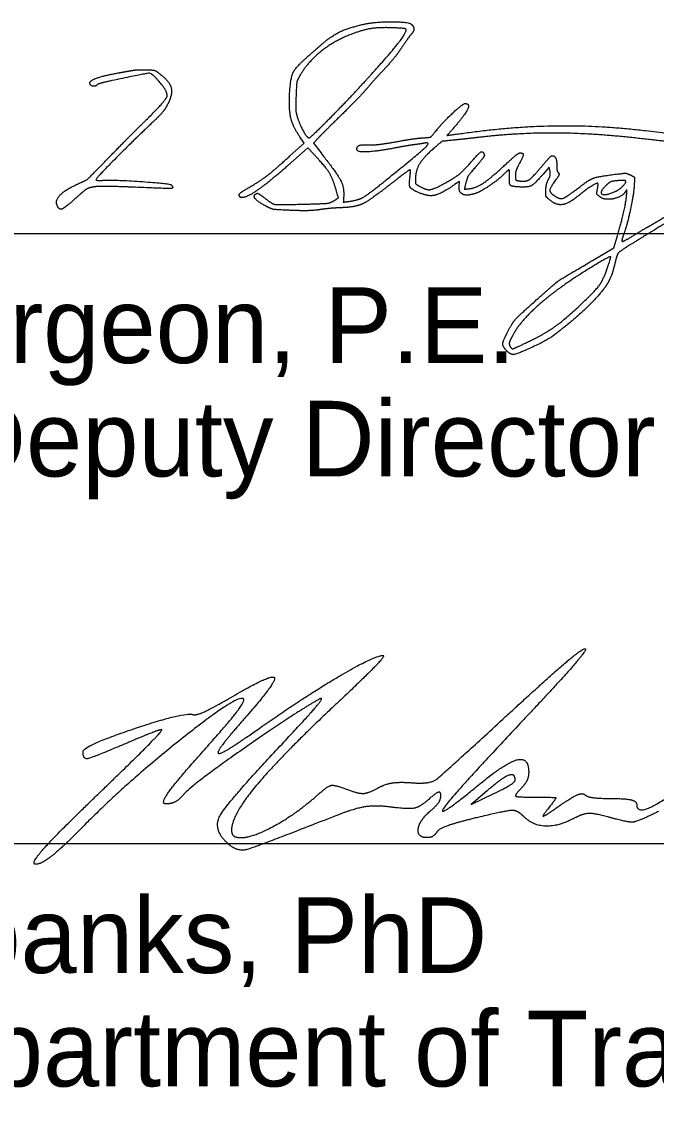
# Model space of a CAD drawing. Extents: x 0 to 34, y 0 to 22.
# Drawn here: x 25.538 to 26.712, y 5.969 to 7.983 of the extents above; entities that cross this region are included whole.
import ezdxf

# ---------------------------------------------------------------- set-up
doc = ezdxf.new("R2010")
doc.units = 0
doc.layers.add('SH_Data', color=7, linetype='Continuous')
doc.layers.add('SH_Text', color=7, linetype='Continuous')

msp = doc.modelspace()

# ---------------------------------------------------------------- linework, layer by layer
at = {"layer": 'SH_Data'}
for p, q in [((24.4745, 7.5907), (27.9745, 7.5907)), ((24.4745, 6.4613), (27.9745, 6.4613))]:
    msp.add_line(p, q, dxfattribs=at)
for points in [[(26.0343, 7.7342), (26.0607, 7.758), (26.0526, 7.7697)], [(26.0877, 7.7684), (26.0776, 7.758), (26.0893, 7.7429)], [(26.0783, 7.7374), (26.0674, 7.7489), (26.0305, 7.7162)], [(26.5156, 7.7054), (26.5143, 7.7133), (26.5027, 7.7002)], [(26.3475, 7.6783), (26.3479, 7.6871), (26.339, 7.681)], [(26.5943, 7.5406), (26.6335, 7.5637), (26.6403, 7.5865)]]:
    msp.add_lwpolyline(points, dxfattribs=at)
for points in [[(26.0927, 7.9404), (26.1103, 7.956), (26.142, 7.9714), (26.1696, 7.9777)], [(26.1696, 7.9777), (26.1908, 7.9826), (26.2538, 7.9826), (26.2591, 7.9778)], [(26.2591, 7.9778), (26.2638, 7.9735), (26.2637, 7.9649), (26.2588, 7.9595)], [(26.1451, 7.9583), (26.1151, 7.9466), (26.0672, 7.9077), (26.0534, 7.884)], [(26.2257, 7.9713), (26.1998, 7.9724), (26.1679, 7.9673), (26.1451, 7.9583)], [(26.2119, 7.9155), (26.2286, 7.9344), (26.2493, 7.9628), (26.2495, 7.9672)], [(26.2495, 7.9672), (26.2496, 7.9693), (26.2423, 7.9706), (26.2257, 7.9713)], [(26.2588, 7.9595), (26.2568, 7.9573), (26.249, 7.9464), (26.2415, 7.9353)], [(26.0742, 7.9244), (26.0819, 7.9311), (26.0902, 7.9382), (26.0927, 7.9404)], [(26.2415, 7.9353), (26.234, 7.9241), (26.2202, 7.9069), (26.2109, 7.8971)], [(26.0334, 7.8443), (26.0349, 7.8786), (26.0459, 7.9001), (26.0742, 7.9244)], [(26.1013, 7.797), (26.1287, 7.8244), (26.178, 7.8771), (26.2119, 7.9155)], [(25.7419, 7.8924), (25.7478, 7.8934), (25.7597, 7.894), (25.7686, 7.8937)], [(25.7686, 7.8937), (25.7822, 7.8932), (25.7861, 7.8919), (25.7949, 7.885)], [(26.2109, 7.8971), (26.2016, 7.8873), (26.1866, 7.8706), (26.1776, 7.8602)], [(25.6643, 7.867), (25.6634, 7.8687), (25.6643, 7.8714), (25.6664, 7.8732)], [(25.6664, 7.8732), (25.6704, 7.8767), (25.6966, 7.8843), (25.718, 7.8881)], [(25.7047, 7.8735), (25.6904, 7.8704), (25.678, 7.8669), (25.6772, 7.8657)], [(25.7911, 7.8733), (25.7791, 7.8872), (25.7674, 7.8872), (25.7047, 7.8735)], [(25.718, 7.8881), (25.7253, 7.8894), (25.7361, 7.8913), (25.7419, 7.8924)], [(25.7684, 7.8009), (25.8042, 7.8359), (25.8093, 7.8522), (25.7911, 7.8733)], [(25.7949, 7.885), (25.8131, 7.8705), (25.8169, 7.8451), (25.8043, 7.8229)], [(26.0534, 7.884), (26.0476, 7.874), (26.0465, 7.8688), (26.0455, 7.8447)], [(25.6772, 7.8657), (25.6752, 7.8627), (25.6662, 7.8636), (25.6643, 7.867)], [(26.1776, 7.8602), (26.1686, 7.8497), (26.1469, 7.8271), (26.1295, 7.81)], [(26.0526, 7.7697), (26.0403, 7.7873), (26.0323, 7.8184), (26.0334, 7.8443)], [(26.0455, 7.8447), (26.0446, 7.8241), (26.0454, 7.8136), (26.0486, 7.8038)], [(25.8043, 7.8229), (25.8017, 7.8184), (25.7895, 7.8052), (25.777, 7.7934)], [(26.3073, 7.7838), (26.3189, 7.7982), (26.3549, 7.8314), (26.3585, 7.8312)], [(26.3585, 7.8312), (26.3677, 7.8308), (26.3594, 7.8121), (26.34, 7.7892)], [(25.777, 7.7934), (25.7404, 7.7588), (25.6742, 7.6915), (25.6752, 7.6898)], [(25.7051, 7.7373), (25.7254, 7.7581), (25.7539, 7.7868), (25.7684, 7.8009)], [(26.0486, 7.8038), (26.053, 7.7904), (26.0663, 7.7676), (26.0697, 7.7674)], [(26.0697, 7.7674), (26.0708, 7.7674), (26.085, 7.7807), (26.1013, 7.797)], [(26.1295, 7.81), (26.112, 7.7928), (26.0932, 7.7741), (26.0877, 7.7684)], [(26.2783, 7.7675), (26.294, 7.7686), (26.2956, 7.7696), (26.3073, 7.7838)], [(26.34, 7.7892), (26.3252, 7.7718), (26.3244, 7.7721), (26.3703, 7.7782)], [(26.3703, 7.7782), (26.4917, 7.7944), (26.7153, 7.7829), (26.8721, 7.7525)], [(26.6857, 7.766), (26.598, 7.776), (26.4573, 7.7771), (26.383, 7.7684)], [(26.1582, 7.7463), (26.1585, 7.7522), (26.1672, 7.7553), (26.1819, 7.7546)], [(26.1819, 7.7546), (26.1891, 7.7543), (26.2103, 7.7568), (26.2291, 7.7602)], [(26.2107, 7.6883), (26.2753, 7.7404), (26.296, 7.7609), (26.2805, 7.7573)], [(26.2652, 7.755), (26.2594, 7.7543), (26.2427, 7.7515), (26.2281, 7.7487)], [(26.2291, 7.7602), (26.2478, 7.7636), (26.2699, 7.7669), (26.2783, 7.7675)], [(26.2805, 7.7573), (26.2779, 7.7567), (26.2711, 7.7557), (26.2652, 7.755)], [(26.338, 7.7634), (26.316, 7.7612), (26.3153, 7.7609), (26.2994, 7.7471)], [(26.383, 7.7684), (26.3706, 7.7669), (26.3504, 7.7647), (26.338, 7.7634)], [(26.7749, 7.7563), (26.7583, 7.7579), (26.7182, 7.7623), (26.6857, 7.766)], [(25.6405, 7.6817), (25.6583, 7.6898), (25.6619, 7.6929), (25.7051, 7.7373)], [(25.9572, 7.675), (25.9807, 7.6889), (26.0019, 7.7051), (26.0343, 7.7342)], [(26.1186, 7.6749), (26.113, 7.6937), (26.0989, 7.7155), (26.0783, 7.7374)], [(26.0893, 7.7429), (26.1215, 7.7017), (26.135, 7.6757), (26.1336, 7.6572)], [(26.2281, 7.7487), (26.1928, 7.7421), (26.158, 7.7409), (26.1582, 7.7463)], [(26.2994, 7.7471), (26.2812, 7.7313), (26.2671, 7.7079), (26.2665, 7.6924)], [(26.371, 7.7245), (26.3841, 7.7397), (26.3918, 7.7435), (26.394, 7.7359)], [(26.394, 7.7359), (26.3944, 7.7343), (26.3884, 7.7257), (26.3805, 7.7168)], [(26.4348, 7.7197), (26.4468, 7.7309), (26.4582, 7.7399), (26.4601, 7.7399)], [(26.4601, 7.7399), (26.4664, 7.7396), (26.4659, 7.733), (26.4584, 7.7192)], [(26.5012, 7.7158), (26.5092, 7.7255), (26.5171, 7.7338), (26.5186, 7.7343)], [(26.5186, 7.7343), (26.5233, 7.7356), (26.5284, 7.7256), (26.5281, 7.7157)], [(26.0305, 7.7162), (25.9965, 7.6862), (25.9539, 7.6566), (25.9451, 7.657)], [(26.3167, 7.6814), (26.3391, 7.6936), (26.355, 7.7062), (26.371, 7.7245)], [(26.3805, 7.7168), (26.3661, 7.7003), (26.3621, 7.6936), (26.3588, 7.68)], [(26.3667, 7.6736), (26.3793, 7.6751), (26.4064, 7.6934), (26.4348, 7.7197)], [(26.4584, 7.7192), (26.454, 7.711), (26.4512, 7.7021), (26.4515, 7.6972)], [(26.4599, 7.6877), (26.4711, 7.6861), (26.4839, 7.6948), (26.5012, 7.7158)], [(26.5281, 7.7157), (26.5279, 7.7106), (26.5291, 7.7049), (26.5307, 7.7032)], [(26.2561, 7.7086), (26.2551, 7.7083), (26.2369, 7.6946), (26.2157, 7.6781)], [(26.2694, 7.6676), (26.2581, 7.673), (26.2547, 7.6805), (26.2565, 7.6964)], [(26.2565, 7.6964), (26.2573, 7.7034), (26.2571, 7.7089), (26.2561, 7.7086)], [(26.2665, 7.6924), (26.2661, 7.6842), (26.2673, 7.6819), (26.2736, 7.6783)], [(26.4312, 7.7013), (26.4218, 7.6916), (26.3893, 7.669), (26.3799, 7.6655)], [(26.4404, 7.6961), (26.4409, 7.7078), (26.4387, 7.709), (26.4312, 7.7013)], [(26.4604, 7.6766), (26.4449, 7.6773), (26.4398, 7.6822), (26.4404, 7.6961)], [(26.4515, 7.6972), (26.4519, 7.6901), (26.4531, 7.6887), (26.4599, 7.6877)], [(26.5027, 7.7002), (26.4864, 7.6819), (26.4758, 7.676), (26.4604, 7.6766)], [(26.5125, 7.6901), (26.5151, 7.6946), (26.5163, 7.7007), (26.5156, 7.7054)], [(26.5307, 7.7032), (26.5329, 7.7008), (26.5319, 7.6977), (26.5266, 7.6903)], [(26.5711, 7.6772), (26.5879, 7.6901), (26.604, 7.696), (26.6327, 7.6997)], [(26.6327, 7.6997), (26.6529, 7.7022), (26.6579, 7.7021), (26.6644, 7.6989)], [(26.6644, 7.6989), (26.6715, 7.6954), (26.6721, 7.694), (26.6715, 7.6819)], [(25.6045, 7.6403), (25.5988, 7.6504), (25.6167, 7.6709), (25.6405, 7.6817)], [(25.6706, 7.6767), (25.6612, 7.6749), (25.6544, 7.6706), (25.6378, 7.6558)], [(25.7475, 7.6761), (25.7118, 7.6776), (25.6772, 7.6779), (25.6706, 7.6767)], [(25.6752, 7.6898), (25.6757, 7.6889), (25.6824, 7.6886), (25.6901, 7.6891)], [(25.6901, 7.6891), (25.7081, 7.6902), (25.8121, 7.6831), (25.8144, 7.6807)], [(25.8144, 7.6807), (25.8202, 7.6743), (25.8088, 7.6735), (25.7475, 7.6761)], [(25.9404, 7.6608), (25.9396, 7.663), (25.9458, 7.6683), (25.9572, 7.675)], [(26.1187, 7.6531), (26.124, 7.6567), (26.124, 7.6569), (26.1186, 7.6749)], [(26.1429, 7.6499), (26.1607, 7.6523), (26.1786, 7.6624), (26.2107, 7.6883)], [(26.2157, 7.6781), (26.1935, 7.661), (26.1717, 7.6463), (26.1646, 7.6437)], [(26.339, 7.681), (26.3138, 7.6634), (26.2886, 7.6586), (26.2694, 7.6676)], [(26.2736, 7.6783), (26.2861, 7.6711), (26.2997, 7.6721), (26.3167, 7.6814)], [(26.3501, 7.6662), (26.3484, 7.668), (26.3473, 7.6734), (26.3475, 7.6783)], [(26.3588, 7.68), (26.3569, 7.6725), (26.3571, 7.6725), (26.3667, 7.6736)], [(26.5078, 7.6709), (26.5081, 7.6774), (26.5102, 7.686), (26.5125, 7.6901)], [(26.5266, 7.6903), (26.5159, 7.6755), (26.5143, 7.6675), (26.5211, 7.6623)], [(26.5211, 7.6623), (26.5326, 7.6535), (26.5453, 7.6573), (26.5711, 7.6772)], [(26.6035, 7.6836), (26.6009, 7.6837), (26.5812, 7.6713), (26.5733, 7.6645)], [(26.6076, 7.6587), (26.6026, 7.6626), (26.6019, 7.6649), (26.6035, 7.6734)], [(26.6035, 7.6734), (26.6045, 7.6789), (26.6045, 7.6835), (26.6035, 7.6836)], [(26.62, 7.6801), (26.6068, 7.6675), (26.6163, 7.6598), (26.6352, 7.6678)], [(26.6407, 7.6883), (26.631, 7.6875), (26.6254, 7.6852), (26.62, 7.6801)], [(26.6352, 7.6678), (26.6436, 7.6714), (26.6576, 7.6856), (26.6552, 7.6882)], [(26.6552, 7.6882), (26.6546, 7.6889), (26.648, 7.689), (26.6407, 7.6883)], [(26.6715, 7.6819), (26.6708, 7.6661), (26.6594, 7.6105), (26.6532, 7.5928)], [(25.6378, 7.6558), (25.6179, 7.6381), (25.6082, 7.6336), (25.6045, 7.6403)], [(25.9451, 7.657), (25.9432, 7.6571), (25.941, 7.6588), (25.9404, 7.6608)], [(25.9916, 7.6402), (25.9745, 7.6491), (25.9654, 7.6608), (25.9725, 7.6648)], [(25.9725, 7.6648), (25.9738, 7.6655), (25.9793, 7.6626), (25.9848, 7.6583)], [(25.9848, 7.6583), (26.0014, 7.6453), (26.0103, 7.6436), (26.0547, 7.6447)], [(26.0547, 7.6447), (26.0972, 7.6457), (26.1101, 7.6474), (26.1187, 7.6531)], [(26.1336, 7.6572), (26.133, 7.6487), (26.1331, 7.6486), (26.1429, 7.6499)], [(26.3799, 7.6655), (26.3686, 7.6614), (26.3542, 7.6617), (26.3501, 7.6662)], [(26.514, 7.6534), (26.5085, 7.6581), (26.5074, 7.6614), (26.5078, 7.6709)], [(26.5733, 7.6645), (26.5524, 7.6466), (26.5273, 7.6419), (26.514, 7.6534)], [(26.6215, 7.6539), (26.6171, 7.654), (26.6109, 7.6562), (26.6076, 7.6587)], [(26.6547, 7.6673), (26.6508, 7.6612), (26.6318, 7.6535), (26.6215, 7.6539)], [(26.6403, 7.5865), (26.6483, 7.6133), (26.6571, 7.6529), (26.6575, 7.6641)], [(26.6575, 7.6641), (26.6577, 7.671), (26.6574, 7.6714), (26.6547, 7.6673)], [(26.0361, 7.6333), (26.0082, 7.6345), (26, 7.6358), (25.9916, 7.6402)], [(26.0888, 7.6346), (26.0786, 7.633), (26.0549, 7.6325), (26.0361, 7.6333)], [(26.1298, 7.6383), (26.1174, 7.6378), (26.099, 7.6361), (26.0888, 7.6346)], [(26.1646, 7.6437), (26.1578, 7.6413), (26.1421, 7.6388), (26.1298, 7.6383)], [(26.7047, 7.6073), (26.7163, 7.6137), (26.7457, 7.6334), (26.7579, 7.643)], [(26.7525, 7.6253), (26.7442, 7.6193), (26.7163, 7.6015), (26.6905, 7.5859)], [(26.6532, 7.5928), (26.6507, 7.5859), (26.6486, 7.5787), (26.6485, 7.5768)], [(26.6693, 7.5864), (26.6809, 7.5935), (26.6968, 7.6029), (26.7047, 7.6073)], [(26.6905, 7.5859), (26.6648, 7.5703), (26.6427, 7.5559), (26.6415, 7.5539)], [(26.6485, 7.5768), (26.6484, 7.575), (26.6578, 7.5793), (26.6693, 7.5864)], [(26.6415, 7.5539), (26.6402, 7.552), (26.6372, 7.5418), (26.6347, 7.5313)], [(26.4902, 7.4674), (26.5257, 7.499), (26.5364, 7.5065), (26.5943, 7.5406)], [(26.6278, 7.5475), (26.6265, 7.5489), (26.5653, 7.5117), (26.5422, 7.4955)], [(26.6099, 7.4989), (26.6144, 7.5065), (26.629, 7.5461), (26.6278, 7.5475)], [(26.6347, 7.5313), (26.6322, 7.5208), (26.6266, 7.506), (26.6222, 7.4983)], [(26.5422, 7.4955), (26.5082, 7.4715), (26.4594, 7.425), (26.4492, 7.4066)], [(26.519, 7.4143), (26.5382, 7.4269), (26.6028, 7.4871), (26.6099, 7.4989)], [(26.6222, 7.4983), (26.6141, 7.484), (26.5632, 7.4331), (26.5378, 7.4139)], [(26.4356, 7.4052), (26.4458, 7.4252), (26.4571, 7.438), (26.4902, 7.4674)], [(26.4739, 7.3894), (26.4883, 7.3962), (26.5085, 7.4074), (26.519, 7.4143)], [(26.5378, 7.4139), (26.5306, 7.4084), (26.5231, 7.4025), (26.521, 7.4008)], [(26.4354, 7.3735), (26.4279, 7.3816), (26.428, 7.3902), (26.4356, 7.4052)], [(26.4492, 7.4066), (26.4443, 7.3978), (26.4402, 7.3891), (26.4401, 7.3871)], [(26.521, 7.4008), (26.5135, 7.3945), (26.453, 7.3662), (26.4474, 7.3665)], [(26.4474, 7.3665), (26.4442, 7.3666), (26.4388, 7.3698), (26.4354, 7.3735)], [(26.4401, 7.3871), (26.44, 7.384), (26.4446, 7.3771), (26.4469, 7.377)], [(26.4469, 7.377), (26.4475, 7.377), (26.4596, 7.3826), (26.4739, 7.3894)]]:
    msp.add_open_spline(points, degree=2, dxfattribs=at)
at = {"layer": 'SH_Text'}
for p, q in [((26.4511, 6.5785), (26.4511, 6.5785)), ((25.674, 6.5474), (25.674, 6.5474))]:
    msp.add_line(p, q, dxfattribs=at)
msp.add_lwpolyline([(26.3994, 6.5588), (26.3698, 6.5332), (26.4105, 6.5528)], dxfattribs=at)
for points in [[(25.9792, 6.6755), (26.0598, 6.7322), (26.1911, 6.8094), (26.2068, 6.8094)], [(26.2068, 6.8094), (26.2117, 6.8094), (26.1704, 6.7668), (26.115, 6.7147)], [(26.4335, 6.696), (26.5085, 6.7651), (26.5745, 6.8217), (26.5803, 6.8217)], [(26.5803, 6.8217), (26.586, 6.8218), (26.534, 6.7617), (26.4646, 6.6881)], [(25.9203, 6.729), (25.999, 6.7752), (26.0113, 6.762), (25.952, 6.6947)], [(25.9483, 6.7288), (25.9387, 6.7384), (25.729, 6.5715), (25.6511, 6.4922)], [(26.0886, 6.7284), (26.0396, 6.7006), (25.8512, 6.5684), (25.838, 6.5524)], [(25.8546, 6.6998), (25.8602, 6.698), (25.8897, 6.7112), (25.9203, 6.729)], [(25.8705, 6.6284), (25.9168, 6.6802), (25.9518, 6.7253), (25.9483, 6.7288)], [(26.0234, 6.6494), (26.0696, 6.6987), (26.0989, 6.7342), (26.0886, 6.7284)], [(26.115, 6.7147), (26.0154, 6.621), (25.9261, 6.5128), (25.9261, 6.4858)], [(25.6513, 6.6313), (25.6515, 6.6418), (25.8389, 6.705), (25.8546, 6.6998)], [(25.952, 6.6947), (25.924, 6.6628), (25.9011, 6.6332), (25.9011, 6.6287)], [(26.2585, 6.5736), (26.292, 6.5708), (26.3155, 6.5872), (26.4335, 6.696)], [(26.4646, 6.6881), (26.3351, 6.5505), (26.303, 6.5033), (26.3852, 6.571)], [(25.674, 6.5474), (25.745, 6.6159), (25.8003, 6.6719), (25.7969, 6.6719)], [(25.7969, 6.6719), (25.7935, 6.6719), (25.7644, 6.6606), (25.7323, 6.6469)], [(25.9011, 6.6287), (25.9011, 6.6243), (25.9363, 6.6453), (25.9792, 6.6755)], [(25.7323, 6.6469), (25.6697, 6.6201), (25.651, 6.6164), (25.6513, 6.6313)], [(25.9163, 6.4638), (25.8911, 6.489), (25.92, 6.5391), (26.0234, 6.6494)], [(25.8047, 6.5344), (25.7944, 6.5344), (25.8233, 6.5757), (25.8705, 6.6284)], [(26.6761, 6.5329), (26.6761, 6.5101), (26.7714, 6.5715), (26.8417, 6.6397)], [(26.3852, 6.571), (26.4336, 6.6109), (26.4761, 6.6212), (26.4761, 6.5931)], [(26.4511, 6.5785), (26.4511, 6.5919), (26.427, 6.5828), (26.3994, 6.5588)], [(26.4761, 6.5931), (26.4761, 6.5842), (26.4693, 6.5701), (26.4611, 6.5619)], [(26.0836, 6.5494), (26.1039, 6.5674), (26.1168, 6.5701), (26.1405, 6.561)], [(26.1955, 6.5631), (26.2089, 6.5707), (26.2372, 6.5754), (26.2585, 6.5736)], [(26.4105, 6.5528), (26.4328, 6.5637), (26.4511, 6.5752), (26.4511, 6.5785)], [(25.5636, 6.4226), (25.5533, 6.4228), (25.6029, 6.479), (25.674, 6.5474)], [(25.838, 6.5524), (25.8298, 6.5425), (25.8148, 6.5344), (25.8047, 6.5344)], [(25.9441, 6.4719), (25.9659, 6.4719), (26.0472, 6.5171), (26.0836, 6.5494)], [(26.1405, 6.561), (26.1607, 6.5534), (26.1795, 6.5541), (26.1955, 6.5631)], [(26.3136, 6.5504), (26.3136, 6.5575), (26.3034, 6.5541), (26.291, 6.5428)], [(26.2948, 6.5219), (26.3052, 6.5305), (26.3136, 6.5433), (26.3136, 6.5504)], [(26.4611, 6.5619), (26.4494, 6.5502), (26.4553, 6.5469), (26.4876, 6.5469)], [(26.4876, 6.5469), (26.5252, 6.5469), (26.5275, 6.5448), (26.512, 6.5255)], [(26.5338, 6.5314), (26.5552, 6.5464), (26.5759, 6.5554), (26.5798, 6.5515)], [(26.5798, 6.5515), (26.5837, 6.5476), (26.607, 6.5444), (26.6315, 6.5444)], [(26.6315, 6.5444), (26.656, 6.5444), (26.6761, 6.5392), (26.6761, 6.5329)], [(26.2215, 6.5284), (26.1923, 6.5322), (26.1525, 6.5257), (26.116, 6.5113)], [(26.291, 6.5428), (26.2754, 6.5287), (26.2541, 6.5243), (26.2215, 6.5284)], [(26.512, 6.5255), (26.5, 6.5105), (26.5065, 6.5123), (26.5338, 6.5314)], [(26.116, 6.5113), (25.9699, 6.4536), (25.9349, 6.4453), (25.9163, 6.4638)], [(26.2879, 6.4719), (26.2695, 6.4719), (26.2741, 6.5046), (26.2948, 6.5219)], [(26.3822, 6.5094), (26.3438, 6.5002), (26.3095, 6.488), (26.306, 6.4823)], [(26.4665, 6.5115), (26.4554, 6.5226), (26.4353, 6.5221), (26.3822, 6.5094)], [(26.5628, 6.509), (26.5321, 6.4925), (26.4842, 6.4938), (26.4665, 6.5115)], [(26.6273, 6.5091), (26.6004, 6.5168), (26.5773, 6.5167), (26.5628, 6.509)], [(26.7164, 6.5204), (26.679, 6.5019), (26.6604, 6.4995), (26.6273, 6.5091)], [(25.6511, 6.4922), (25.6133, 6.4537), (25.5739, 6.4224), (25.5636, 6.4226)], [(25.9261, 6.4858), (25.9261, 6.4782), (25.9342, 6.4719), (25.9441, 6.4719)], [(26.306, 6.4823), (26.3025, 6.4766), (26.2943, 6.4719), (26.2879, 6.4719)]]:
    msp.add_open_spline(points, degree=2, dxfattribs=at)

# ---------------------------------------------------------------- texts
for s, p in [('Jason L. Sturgeon, P.E.', (24.4745, 7.3507)), ('District       Deputy Director', (24.4745, 7.1407)), ('Jack Marchbanks, PhD', (24.4745, 6.2213)), ('Director, Department of Transportation', (24.4745, 6.0113))]:
    msp.add_text(s, height=0.14, dxfattribs=at).set_placement(p)

doc.saveas('drawing.dxf')
